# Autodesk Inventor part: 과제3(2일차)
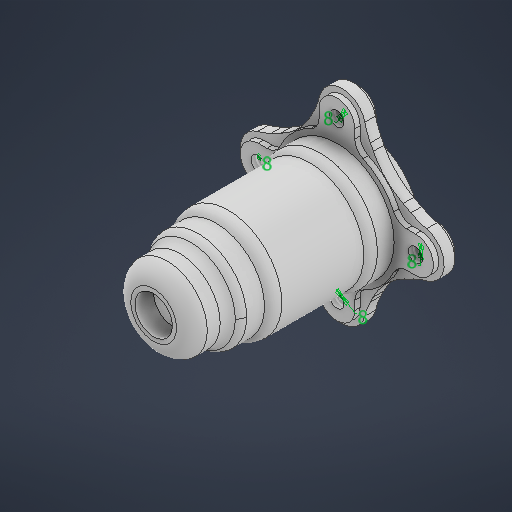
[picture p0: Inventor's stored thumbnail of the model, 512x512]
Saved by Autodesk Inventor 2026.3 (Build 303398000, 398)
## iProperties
Created: 2026-08
Part Number: 과제3(2일차)
Material: 일반
Document SubType Name: Modeling
Designer: chang
Density: 1 g/cm^3
Appearance: 기본값
Author: chang
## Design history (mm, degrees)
sketch "스케치1"
  geometry: C1 r 22.5 at (0, 0); C2 r 10.5 at (0, 0); 1 further point
  constraints: 2 centre point, 2 coincident
  dimensions: "d0" = 45 diameter of C1; "d1" = 21 diameter of C2
extrude "돌출1" new body sketch "스케치1" distance "d2" = 7.5; taper "d3" = 0 deg
fillet "모깎기1" dims "d4" = 10
sketch "스케치2"
  geometry: C1 r 10.5 at (0, 0); C2 r 22.5 at (0, 0) reference; C3 r 22.5 at (0, 0); 1 further point
  constraints: 2 centre point, 2 coincident
  dimensions: "d5" = 21 diameter of C1
extrude "돌출2" join sketch "스케치2" distance "d6" = 3; taper "d7" = 0 deg
sketch "스케치3"
  geometry: C1 r 10.5 at (0, 0) reference; C2 r 16 at (0, 0); C3 r 22.5 at (0, 0); 1 further point
  constraints: 2 centre point, 2 coincident
  dimensions: "d8" = 32 diameter of C2
extrude "돌출3" join sketch "스케치3" distance "d9" = 12; taper "d10" = 0 deg
sketch "스케치4"
  geometry: 1 further point
sketch "스케치5"
  geometry: C1 r 10.5 at (0, 0) reference; C2 r 17.5 at (0, 0); C3 r 27 at (0, 0); 1 further point
  constraints: 2 centre point, 2 coincident
  dimensions: "d11" = 35 diameter of C2; "d12" = 54 diameter of C3
extrude "돌출4" join sketch "스케치5" distance "d13" = 2.5; taper "d14" = 0 deg
fillet "모깎기2" dims "d15" = 9
sketch "스케치6"
  geometry: C1 r 17.5 at (0, 0); C2 r 27 at (0, 0); 1 further point
  constraints: 2 centre point, 2 coincident
  dimensions: "d16" = 35 diameter of C1; "d17" = 54 diameter of C2
extrude "돌출5" join sketch "스케치6" distance "d18" = 2.5; taper "d19" = 0 deg
sketch "스케치7"
  geometry: C1 r 21 at (0, 0); C2 r 27 at (0, 0); 1 further point
  constraints: 2 centre point, 2 coincident
  dimensions: "d20" = 42 diameter of C1
extrude "돌출6" join sketch "스케치7" distance "d21" = 7.5; taper "d22" = 0 deg
sketch "스케치8"
  geometry: C1 r 21 at (0, 0); C2 r 30 at (0, 0); 1 further point
  constraints: 2 centre point, 2 coincident
  dimensions: "d23" = 42 diameter of C1; "d24" = 60 diameter of C2
extrude "돌출7" join sketch "스케치8" distance "d25" = 7.5; taper "d26" = 0 deg
fillet "모깎기3" dims "d27" = 9
sketch "스케치9"
  geometry: C1 r 24 at (0, 0); C2 r 30 at (0, 0); 1 further point
  constraints: 2 centre point, 2 coincident
  dimensions: "d28" = 48 diameter of C1; "d29" = 60 diameter of C2
extrude "돌출8" join sketch "스케치9" distance "d30" = 45; taper "d31" = 0 deg
sketch "스케치10"
  geometry: C1 r 32 at (0, 0); C2 r 24 at (0, 0); 1 further point
  constraints: 2 centre point, 2 coincident
  dimensions: "d32" = 64 diameter of C1; "d33" = 48 diameter of C2
extrude "돌출9" join sketch "스케치10" distance "d34" = 15; taper "d35" = 0 deg
fillet "모깎기4" dims "d36" = 9
sketch "스케치11"
  geometry: C1 r 17.5 at (0, 0); C2 r 10.5 at (0, 0) reference; 3 further points
  constraints: 1 centre point, 1 coincident, 1 other
  dimensions: "d37" = 35 diameter of C1
sketch "스케치12"
  geometry: L1 (10, -44)-(10, -39.051); L2 (-10, -44)-(-10, -39.051); L3 (44, 10)-(39.051, 10); L4 (44, -10)-(39.051, -10); L5 (-10, 44)-(-10, 39.051); L6 (10, 44)-(10, 39.051); L7 (-44, -10)-(-39.051, -10); L8 (-44, 10)-(-39.051, 10); C1 r 4 at (0, -44); C2 r 4 at (44, 0); C3 r 4 at (0, 44); C4 r 4 at (-44, 0); C5 r 21 at (0, 0); A1 r 10 centre (0, -44) between (-10, -44) and (10, -44); A2 r 8 centre (18, -39.051) between (14.651, -31.786) and (10, -39.051); A3 r 8 centre (-18, -39.051) between (-10, -39.051) and (-14.651, -31.786); A4 r 10 centre (44, 0) between (44, -10) and (44, 10); A5 r 8 centre (39.051, 18) between (31.786, 14.651) and (39.051, 10); A6 r 8 centre (39.051, -18) between (39.051, -10) and (31.786, -14.651); A7 r 10 centre (0, 44) between (10, 44) and (-10, 44); A8 r 8 centre (-18, 39.051) between (-14.651, 31.786) and (-10, 39.051); A9 r 8 centre (18, 39.051) between (10, 39.051) and (14.651, 31.786); A10 r 10 centre (-44, 0) between (-44, 10) and (-44, -10); A11 r 8 centre (-39.051, -18) between (-31.786, -14.651) and (-39.051, -10); A12 r 8 centre (-39.051, 18) between (-39.051, 10) and (-31.786, 14.651); A13 r 35 centre (0, 0) between (14.651, -31.786) and (31.786, -14.651); A14 r 35 centre (0, 0) between (31.786, 14.651) and (14.651, 31.786); A15 r 35 centre (0, 0) between (-14.651, 31.786) and (-31.786, 14.651); A16 r 35 centre (0, 0) between (-31.786, -14.651) and (-14.651, -31.786); 9 further points
  constraints: 32 point on circle, 21 centre point, 16 end point, 8 point on line, 6 coincident, 3 tangent, 1 equal radius, 1 parallel, 1 vertical, 73 other
  dimensions: "d44" = 8 diameter of C1; "d45" = 20 diameter of A1; "d47" = 8 radius of A2 (derived); "d50" = 360 deg dimension on point (0, 0) C1.centre (derived); "d52" = 42 diameter of C5
  node "스케치 - 원형 패턴1" dims "d50" = 360 deg (derived)
sketch "스케치13"
  geometry: 1 further point
sketch "스케치14"
  geometry: 1 further point
extrude "돌출10" join sketch "스케치12" distance "d53" = 3; taper "d54" = 0 deg
sketch "스케치15"
  geometry: 1 further point
sketch "스케치16"
  geometry: L1 (38.381, -15.973)-(34.005, -18.288); L2 (15.728, -38.568)-(17.392, -35.256); L3 (15.668, 38.617)-(17.198, 35.531); L4 (34.637, 17.998)-(39.744, 15.433); L5 (0, -44)-(-12.818, -46.167); L6 (-34.637, -17.998)-(-39.744, -15.433); L7 (-15.668, -38.617)-(-17.198, -35.531); L8 (-38.381, 15.973)-(-34.005, 18.288); L9 (-15.728, 38.568)-(-17.392, 35.256); A1 r 35 centre (0, 0) between (21.058, -27.956) and (27.393, -21.786); A2 r 13 centre (0, -44) between (-12.818, -46.167) and (12.645, -47.018); A3 r 13 centre (0, 44) between (12.653, 46.984) and (-12.818, 46.167); A4 r 13 centre (44, 0) between (47.155, -12.611) and (47.312, 12.571) reference; A5 r 39 centre (57.249, 50.284) between (39.744, 15.433) and (47.312, 12.571); A6 r 39 centre (52.141, 52.849) between (17.198, 35.531) and (34.637, 17.998); A7 r 39 centre (50.612, 55.935) between (12.653, 46.984) and (15.668, 38.617); A8 r 39 centre (56.618, -50.446) between (47.155, -12.611) and (38.381, -15.973); A9 r 39 centre (52.243, -52.761) between (34.005, -18.288) and (17.392, -35.256); A10 r 39 centre (50.579, -56.073) between (15.728, -38.568) and (12.645, -47.018); A11 r 13 centre (-44, 0) between (-47.155, 12.611) and (-47.312, -12.571); A12 r 39 centre (-57.249, -50.284) between (-39.744, -15.433) and (-47.312, -12.571); A13 r 39 centre (-52.141, -52.849) between (-17.198, -35.531) and (-34.637, -17.998); A14 r 39 centre (-50.612, -55.935) between (-12.653, -46.984) and (-15.668, -38.617); A15 r 35 centre (0, 0) between (-21.058, 27.956) and (-27.393, 21.786); A16 r 39 centre (-56.618, 50.446) between (-47.155, 12.611) and (-38.381, 15.973); A17 r 39 centre (-52.243, 52.761) between (-34.005, 18.288) and (-17.392, 35.256); A18 r 39 centre (-50.579, 56.073) between (-15.728, 38.568) and (-12.645, 47.018); 12 further points
  constraints: 42 point on circle, 18 centre point, 18 end point, 13 tangent, 12 point on line, 5 equal radius, 1 midpoint, 1 perpendicular, 84 other
  dimensions: "d58" = 26 diameter of A2; "d60" = 39 radius of A5 (derived); "d63" = 360 deg dimension on point (0, 0) A4.centre (derived); "d65" = 35 radius of A1; "d66" = 54.5493 deg angle of L4 L1; "d67" = 36.2626 deg angle of L5 L4; "d68" = 38.80252 distance from line of A1.end L4; "d69" = 47.16005 distance from line of A1.start L4; "d70" = 3.87216 distance from line of A3.end L4
  node "스케치 - 원형 패턴2" dims "d63" = 360 deg (derived)
sketch "스케치17"
  geometry: 1 further point
sketch "스케치18"
  geometry: 1 further point
sketch "스케치19"
  geometry: C1 r 4 at (44, 0); C2 r 4 at (0, 44); C3 r 4 at (-44, 0); C4 r 4 at (0, -44); 1 further point
  constraints: 4 centre point, 4 other
  dimensions: "d71" = 8 diameter of C1; "d72" = 8 diameter of C2; "d73" = 8 diameter of C3; "d74" = 8 diameter of C4
extrude "돌출11" join sketch "스케치16" distance "d75" = 6; taper "d76" = 0 deg
sketch "스케치23"
  geometry: 1 further point
sketch "스케치24"
  geometry: L1 (44, 10)-(37.081, 10); L2 (44, 10)-(39.051, 10) reference; L3 (39.051, -10)-(44, -10) reference; L4 (44, -10)-(37.081, -10); L5 (10, -44)-(10, -37.081); L6 (10, -44)-(10, -39.051) reference; L7 (-10, -44)-(-10, -37.081); L8 (10, 44)-(10, 37.081); L9 (10, 39.051)-(10, 44) reference; L10 (-10, 44)-(-10, 39.051) reference; L11 (-10, 44)-(-10, 37.081); L12 (-44, 10)-(-37.081, 10); L13 (-39.051, 10)-(-44, 10) reference; L14 (-44, -10)-(-37.081, -10); C1 r 4 at (0, -44); C2 r 4 at (0, 44); C3 r 4 at (-44, 0); C4 r 4 at (44, 0); A1 r 10 centre (0, -44) between (-10, -44) and (10, -44); A2 r 10 centre (0, 44) between (10, 44) and (-10, 44); A3 r 10 centre (-44, 0) between (-44, 10) and (-44, -10); A4 r 10 centre (44, 0) between (44, -10) and (44, 10); A5 r 35 centre (0, 0) between (13.125, -32.446) and (32.446, -13.125) reference; A6 r 35 centre (0, 0) between (32.446, 13.125) and (13.125, 32.446) reference; A7 r 35 centre (0, 0) between (-13.125, 32.446) and (-32.446, 13.125) reference; A8 r 35 centre (0, 0) between (-32.446, -13.125) and (-13.125, -32.446) reference; A9 r 5 centre (37.081, 15) between (32.446, 13.125) and (37.081, 10); A10 r 5 centre (37.081, -15) between (37.081, -10) and (32.446, -13.125); A11 r 5 centre (15, -37.081) between (13.125, -32.446) and (10, -37.081); A12 r 5 centre (-15, -37.081) between (-10, -37.081) and (-13.125, -32.446); A13 r 5 centre (-37.081, -15) between (-32.446, -13.125) and (-37.081, -10); A14 r 5 centre (-37.081, 15) between (-37.081, 10) and (-32.446, 13.125); A15 r 5 centre (-15, 37.081) between (-13.125, 32.446) and (-10, 37.081); A16 r 5 centre (15, 37.081) between (10, 37.081) and (13.125, 32.446); 11 further points
  constraints: 41 point on circle, 22 tangent, 20 centre point, 19 end point, 11 point on line, 7 equal radius, 5 coincident, 5 collinear, 2 parallel, 5 other
  dimensions: "d92" = 8 diameter of C1; "d93" = 20 diameter of A1; "d94" = 8 diameter of C2; "d95" = 20 diameter of A2; "d96" = 8 diameter of C3; "d97" = 20 diameter of A3; "d98" = 8 diameter of C4; "d99" = 20 diameter of A4; "d100" = 5 radius of A9
extrude "돌출13" join sketch "스케치24" distance "d101" = 3; taper "d102" = 0 deg
sketch "스케치25"
  geometry: C1 r 4 at (44, 0); 1 further point
  constraints: 1 centre point
extrude "돌출14" cut sketch "스케치25" distance "d103" = 6; taper "d104" = 0 deg
sketch "스케치26"
  geometry: 1 further point
sketch "스케치27"
  geometry: C1 r 4 at (0, 44); C2 r 4 at (0, -44) reference; C3 r 4 at (0, -44); 1 further point
  constraints: 2 centre point, 1 coincident
  dimensions: "d105" = 8 diameter of C1
extrude "돌출15" cut sketch "스케치27" distance "d106" = 6; taper "d107" = 0 deg
sketch "스케치28"
  geometry: C1 r 4 at (0, 44); 1 further point
  constraints: 1 centre point
  dimensions: "d108" = 8 diameter of C1
extrude "돌출16" cut sketch "스케치28" distance "d109" = 6; taper "d110" = 0 deg
sketch "스케치29"
  geometry: 1 further point
sketch "스케치30"
  geometry: C1 r 4 at (-44, 0) reference; C2 r 4 at (-44, 0); 1 further point
  constraints: 1 centre point, 1 coincident
  dimensions: "d111" = 8 diameter of C2
extrude "돌출17" cut sketch "스케치30" distance "d112" = 6; taper "d113" = 0 deg
node "솔리드1"
other parameters: "d56" = 26
